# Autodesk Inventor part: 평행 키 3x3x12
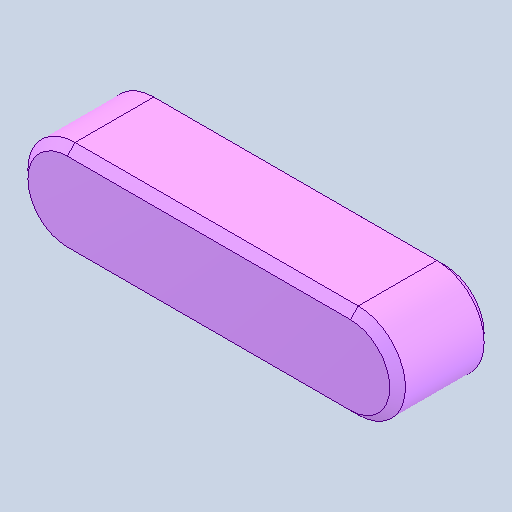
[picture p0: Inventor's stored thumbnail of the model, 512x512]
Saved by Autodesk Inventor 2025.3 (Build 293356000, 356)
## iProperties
Created: 2025-10
Part Number: 평행 키 3x3x12
Material: 강철, 연강
Description: 키 및 해당 키홈
Document SubType Name: Modeling
Designer: USER
Density: 7.85 g/cm^3
Appearance: 기본값
Author: jhkim
Sending System: Autodesk Inventor 2026
Preprocessor: ST-DEVELOPER v20.1
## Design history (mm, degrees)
feature "Solid1"
node "솔리드1"
